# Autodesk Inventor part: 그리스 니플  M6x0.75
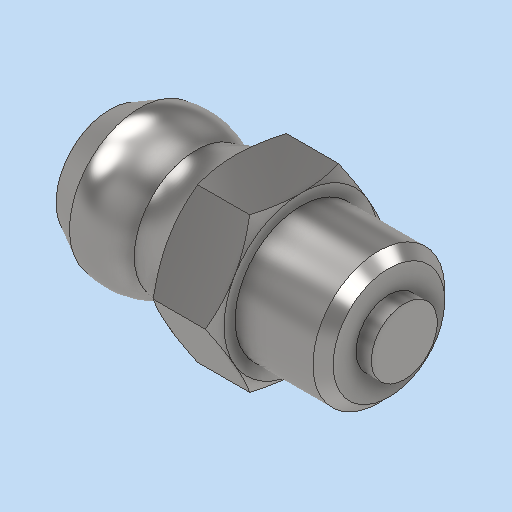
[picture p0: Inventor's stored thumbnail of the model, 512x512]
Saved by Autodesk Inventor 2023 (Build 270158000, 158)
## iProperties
Created: 2024-11
Part Number: 그리스 니플  M6x0.75
Material: 강철, 연강
Description: 윤활 니플, 원추 유형 A
Document SubType Name: Modeling
Designer: asung
Density: 7.85 g/cm^3
Appearance: 기본값
Author: jhkim
Sending System: Autodesk Inventor 2025
Preprocessor: ST-DEVELOPER v20
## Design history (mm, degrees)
feature "Solid1"
node "솔리드1"
